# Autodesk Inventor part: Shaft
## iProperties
Created: 2002-01
Part Number: Shaft
Document SubType Name: Modeling
Designer: ***
Control State: 0
Master: False
Checked Out: False
Shininess: 20.0
Length Units: 11269
Angle Units: 11279
Time Units: 11290
Mass Units: 11283
Length Display Precision: 3
Angle Display Precision: 2
Density: 0.0
Volumn: 0.0
Area: 0.0
PropertySet Name: Model Information
Author: ***
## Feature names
1. Revolution1
2. Extrusion1
3. Extrusion2
4. Hole1
5. Chamfer1
